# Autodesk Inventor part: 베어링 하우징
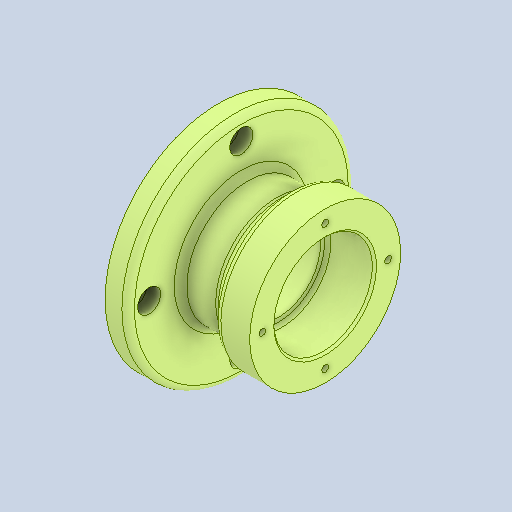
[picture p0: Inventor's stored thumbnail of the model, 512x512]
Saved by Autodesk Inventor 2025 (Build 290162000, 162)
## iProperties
Created: 2026-01
Part Number: 베어링 하우징
Material: 알루미늄 6061
Document SubType Name: Modeling
Designer: KDI
Density: 2.7 g/cm^3
Appearance: 기본값
Author: jhkim
Sending System: Autodesk Inventor 2026
Preprocessor: ST-DEVELOPER v20.1
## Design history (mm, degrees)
feature "솔리드1"
node "솔리드2"
